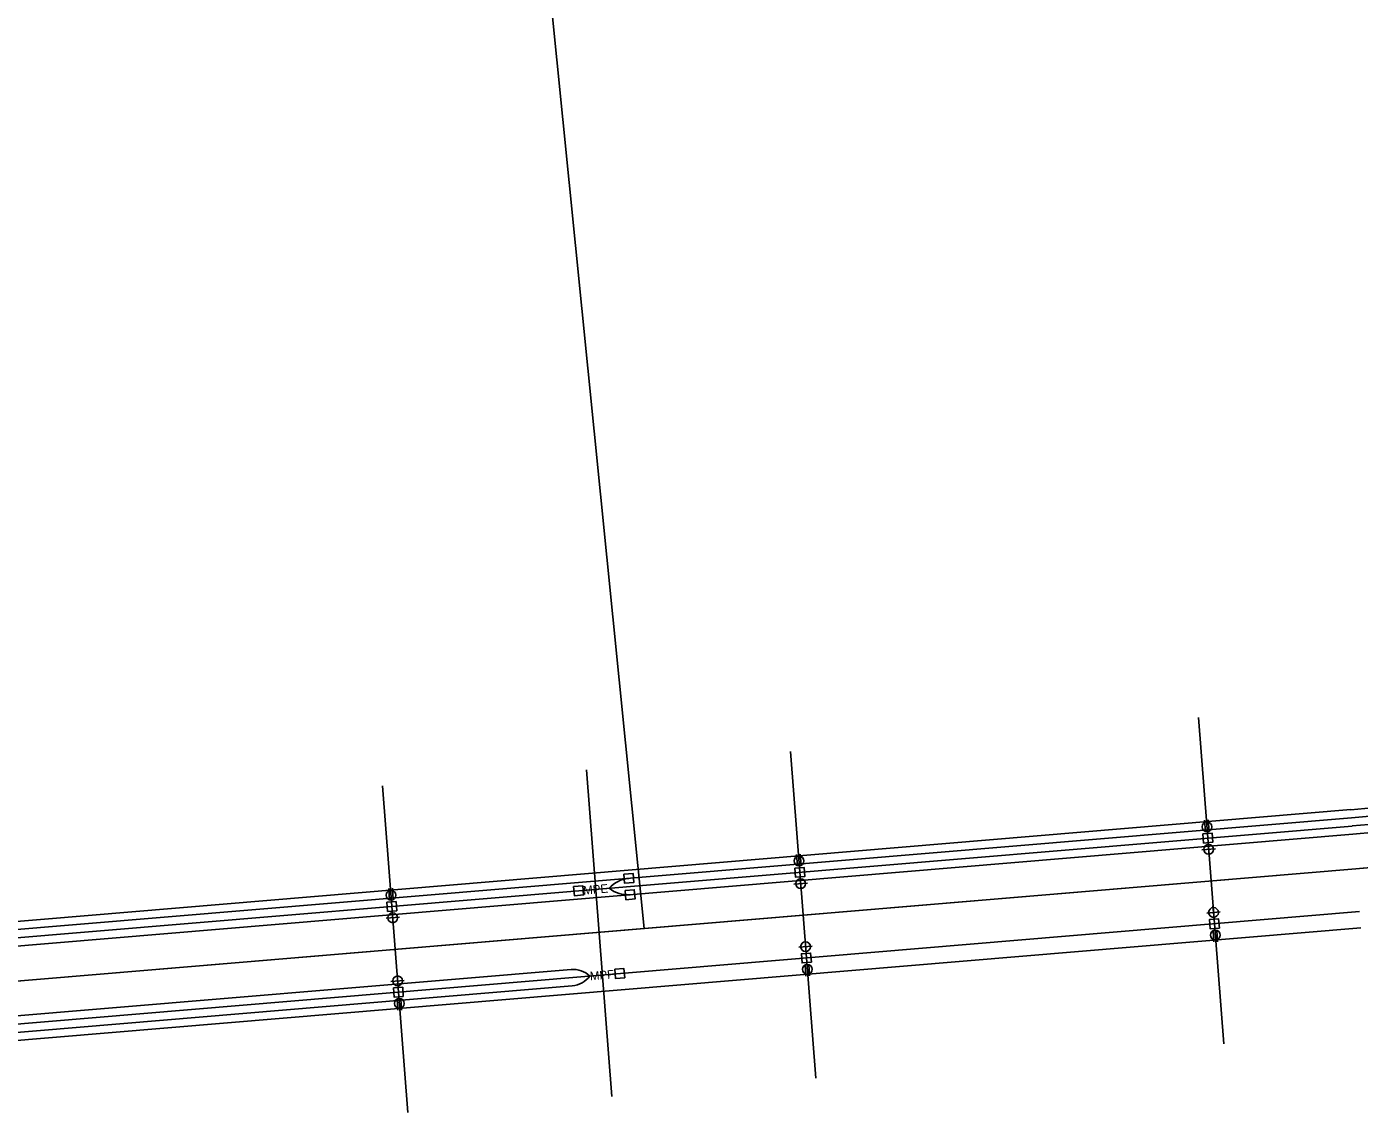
# Model space of a CAD drawing. Extents: x 927222 to 928611, y 636651 to 637029.
# Drawn here: x 928247.7 to 928410.4, y 636763.8 to 636896.4 of the extents above; entities that cross this region are included whole.
import ezdxf

# ---------------------------------------------------------------- set-up
doc = ezdxf.new("R2010")
doc.units = 0
for name, color, linetype in [('Miscellaneous2', 7, 'Continuous'), ('NonPlottingEle_dp', 7, 'Continuous'), ('PoleLight', 7, 'Continuous'), ('TextLabel', 7, 'Continuous')]:
    doc.layers.add(name, color=color, linetype=linetype)

msp = doc.modelspace()

# ---------------------------------------------------------------- linework, layer by layer
at = {"layer": 'Miscellaneous2'}
for p, q in [((928298.74, 637028.99), (928323.09, 636786.25)), ((928393.88, 636772.14), (928390.78, 636812.02)), ((928344.06, 636767.96), (928340.96, 636807.84)), ((928319.15, 636765.73), (928316.06, 636805.61)), ((928294.23, 636763.79), (928291.13, 636803.67)), ((928145.98, 636771.41), (928410, 636793.53)), ((928323.09, 636786.25), (928410, 636793.53)), ((928145.98, 636771.41), (928323.09, 636786.25))]:
    msp.add_line(p, q, dxfattribs=at)
for end in [291.57718, 289.02547]:
    msp.add_arc((928350.92, 637498.56), 707.5, 274.79003, end, dxfattribs=at)
at = {"layer": 'NonPlottingEle_dp'}
for p, q in [((928145.38, 636778.63), (928409.4, 636800.76)), ((928145.46, 636777.64), (928409.48, 636799.76)), ((928145.55, 636776.64), (928409.56, 636798.76)), ((928145.63, 636775.64), (928409.65, 636797.77)), ((928146.42, 636766.18), (928410.44, 636788.3)), ((928146.59, 636764.18), (928410.61, 636786.31)), ((928146.34, 636767.17), (928314.16, 636781.24)), ((928146.51, 636765.18), (928314.32, 636779.24))]:
    msp.add_line(p, q, dxfattribs=at)
for centre, radius, start, end in [((928350.92, 637498.56), 701.25, 274.79003, 288.94268), ((928350.92, 637498.56), 700.25, 274.79003, 288.23668), ((928350.92, 637498.56), 703.25, 274.79003, 288.94327), ((928350.92, 637498.56), 702.25, 274.79003, 285.45574), ((928321.52, 636788.75), 3.62, 94.79, 138.4084), ((928321.08, 636793.98), 3.62, 231.1716, 274.7901), ((928314.41, 636778.26), 2.99, 46.5108, 94.79), ((928314.07, 636782.22), 2.99, 274.79, 323.0693)]:
    msp.add_arc(centre, radius, start, end, dxfattribs=at)
at = {"layer": 'PoleLight'}
for p, q in [((928391.54, 636799.47), (928391.64, 636798.1)), ((928391.99, 636799.5), (928392.09, 636798.13)), ((928391.89, 636797.84), (928391.87, 636798.07)), ((928391.22, 636795.84), (928392.86, 636795.97)), ((928391.97, 636796.72), (928392.1, 636795.08)), ((928341.71, 636795.29), (928341.82, 636793.92)), ((928342.06, 636793.67), (928342.05, 636793.89)), ((928342.16, 636795.33), (928342.27, 636793.96)), ((928342.15, 636792.55), (928342.27, 636790.91)), ((928291.89, 636791.12), (928291.99, 636789.75)), ((928292.34, 636791.15), (928292.44, 636789.78)), ((928341.39, 636791.67), (928343.03, 636791.79)), ((928292.24, 636789.49), (928292.22, 636789.72)), ((928392.69, 636787.38), (928392.56, 636789.02)), ((928291.57, 636787.49), (928293.21, 636787.62)), ((928292.32, 636788.37), (928292.45, 636786.73)), ((928393.45, 636788.26), (928391.81, 636788.13)), ((928392.67, 636784.6), (928392.57, 636785.97)), ((928392.77, 636786.26), (928392.79, 636786.03)), ((928393.12, 636784.63), (928393.02, 636786)), ((928343.62, 636784.08), (928341.98, 636783.96)), ((928342.86, 636783.2), (928342.74, 636784.84)), ((928342.85, 636780.42), (928342.74, 636781.8)), ((928342.95, 636782.08), (928342.97, 636781.86)), ((928343.3, 636780.46), (928343.19, 636781.83)), ((928293.8, 636779.91), (928292.16, 636779.78)), ((928293.04, 636779.03), (928292.91, 636780.67)), ((928293.02, 636776.25), (928292.92, 636777.62)), ((928293.12, 636777.91), (928293.14, 636777.68)), ((928293.47, 636776.28), (928293.37, 636777.65))]:
    msp.add_line(p, q, dxfattribs=at)
for centre in [(928391.83, 636798.66), (928392.04, 636795.9), (928342, 636794.49), (928342.21, 636791.73), (928292.17, 636790.31), (928292.39, 636787.55), (928392.63, 636788.2), (928392.84, 636785.44), (928342.8, 636784.02), (928343.01, 636781.26), (928292.98, 636779.85), (928293.19, 636777.09)]:
    msp.add_circle(centre, 0.597, dxfattribs=at)
at = {"layer": 'TextLabel'}
for points in [[(928391.33, 636797.8), (928392.45, 636797.89), (928392.54, 636796.77), (928391.41, 636796.68)], [(928320.6, 636792.88), (928321.73, 636792.97), (928321.82, 636791.85), (928320.7, 636791.76)], [(928341.5, 636793.63), (928342.62, 636793.71), (928342.71, 636792.59), (928341.59, 636792.5)], [(928314.48, 636791.37), (928315.6, 636791.47), (928315.7, 636790.34), (928314.58, 636790.25)], [(928320.77, 636790.88), (928321.89, 636790.98), (928321.99, 636789.86), (928320.87, 636789.76)], [(928291.68, 636789.45), (928292.8, 636789.54), (928292.88, 636788.42), (928291.76, 636788.33)], [(928393.34, 636786.3), (928392.21, 636786.21), (928392.13, 636787.33), (928393.25, 636787.42)], [(928343.51, 636782.12), (928342.39, 636782.04), (928342.3, 636783.16), (928343.42, 636783.24)], [(928319.51, 636781.26), (928320.63, 636781.35), (928320.73, 636780.23), (928319.6, 636780.13)], [(928293.68, 636777.95), (928292.56, 636777.86), (928292.48, 636778.98), (928293.6, 636779.07)]]:
    msp.add_lwpolyline(points, close=True, dxfattribs=at)

# ---------------------------------------------------------------- texts
at = {"layer": 'PoleLight'}
for s, p in [('MPE', (928315.69, 636790.37)), ('MPF', (928316.51, 636779.9))]:
    msp.add_text(s, height=1.05, rotation=4.9034, dxfattribs=at).set_placement(p)

doc.saveas('drawing.dxf')
